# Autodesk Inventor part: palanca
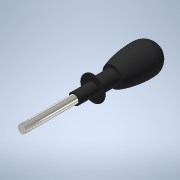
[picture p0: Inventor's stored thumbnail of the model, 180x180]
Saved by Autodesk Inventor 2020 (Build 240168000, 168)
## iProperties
Created: 2018-10
Part Number: palanca
Material: Genérico
Document SubType Name: Modeling
Designer: Pedro
Density: 1 g/cm^3
Appearance: Por defecto
Author: Pedro
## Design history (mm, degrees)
sketch "Boceto1"
  geometry: L1 (-33.716, 6.5)-(-33.716, 12); L2 (-33.716, 12)-(-32.716, 12); L3 (-33.716, 0)-(31.284, 0); L4 (-13.716, 7)-(-29.716, 7); L5 (-32.716, 12)-(-29.716, 7); L6 (-13.716, 7)-(-13.716, 10); L7 (-33.716, 0)-(-103.716, 0); L8 (-103.716, 0)-(-103.716, 4); L9 (-33.716, 6.5)-(-33.716, 5.5); L10 (-33.716, 5.5)-(-51.716, 5.5); L11 (-51.716, 4)-(-51.716, 5.5); L12 (-101.716, 4)-(-101.716, 3.5); L13 (-101.716, 3.5)-(-102.216, 3.5); L14 (-102.216, 3.5)-(-102.216, 4); L15 (-103.716, 4)-(-102.216, 4); L16 (-101.716, 4)-(-51.716, 4); A1 r 14.5 centre (16.784, 0) between (31.284, 0) and (16.784, 14.5); A2 r 85.932 centre (13.873, -71.382) between (16.784, 14.5) and (-13.716, 10); 1 further point
  constraints: 32 end point, 6 perpendicular, 4 parallel, 4 point on circle, 2 centre point, 2 vertical, 1 point on line
revolve "Revolución1" sketch "Boceto1" stored, may be unused: angle "d13" = 90 deg
node "Sólido1"
